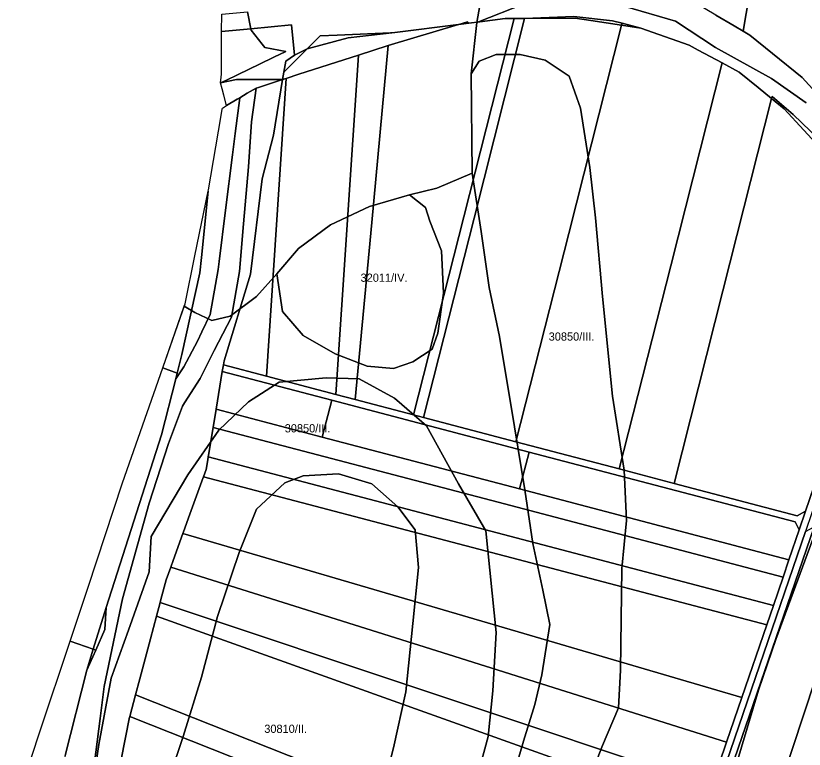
# Model space of a CAD drawing. Extents: x -545779 to -541342, y -1153413 to -1149956.
# Drawn here: x -545548.8 to -545068.2, y -1151704.2 to -1151257.3 of the extents above; entities that cross this region are included whole.
import ezdxf

# ---------------------------------------------------------------- set-up
doc = ezdxf.new("R2010")
doc.units = 0
for name, color, linetype in [('95560013', 7, 'Continuous'), ('95640013', 7, 'Continuous'), ('95660013', 7, 'Continuous')]:
    doc.layers.add(name, color=color, linetype=linetype)

msp = doc.modelspace()

# ---------------------------------------------------------------- linework, layer by layer
at = {"layer": '95560013'}
for points in [[(-545105.44, -1151266.77), (-545111.01, -1151263.46), (-545122.03, -1151256.92), (-545136.05, -1151248.6), (-545152.78, -1151242.45), (-545125.33, -1151080.16), (-545122.66, -1151081.28), (-545114.24, -1151089.6), (-545080.32, -1151118.3)], [(-545105.44, -1151266.77), (-545080.32, -1151118.3), (-545073, -1151124.65), (-545057.67, -1151127.49), (-544996.34, -1151140.83), (-544980.98, -1151144.11), (-544998.72, -1151249.04), (-545016.45, -1151353.98), (-545028.49, -1151339.4), (-545040.16, -1151326.96), (-545069.42, -1151294.93), (-545087.51, -1151280.35), (-545101.41, -1151269.18)], [(-545341.9, -1151491.18), (-545331.84, -1151383.26), (-545321.78, -1151275.35), (-545278.9, -1151262.69), (-545278.74, -1151262.67), (-545272.62, -1151261.89), (-545265.88, -1151261.04), (-545250.45, -1151259.08), (-545245.08, -1151259.05), (-545275.68, -1151379.8), (-545306.28, -1151500.54)], [(-545300.24, -1151502.13), (-545306.28, -1151500.54), (-545275.68, -1151379.8), (-545245.08, -1151259.05), (-545238.63, -1151259.02), (-545269.44, -1151380.59)], [(-545211.74, -1151390), (-545243.89, -1151516.92), (-545300.24, -1151502.13), (-545269.44, -1151380.59), (-545238.63, -1151259.02), (-545207.88, -1151258.87), (-545198.34, -1151260.29), (-545179.58, -1151263.09)], [(-545179.58, -1151263.09), (-545198.34, -1151260.29), (-545207.88, -1151258.87), (-545238.63, -1151259.02), (-545208.57, -1151257.76), (-545185.16, -1151260.43), (-545179.22, -1151261.77)], [(-545243.89, -1151516.92), (-545211.74, -1151390), (-545179.58, -1151263.09), (-545167.85, -1151264.84), (-545138.31, -1151275.29), (-545132.85, -1151278.22), (-545118.25, -1151286.07), (-545149.6, -1151409.76), (-545180.94, -1151533.46)], [(-545179.22, -1151261.77), (-545167.85, -1151264.84), (-545179.58, -1151263.09)], [(-545353.72, -1151488.08), (-545346.84, -1151384.66), (-545339.96, -1151281.24), (-545321.78, -1151275.35), (-545331.84, -1151383.26), (-545341.9, -1151491.18)], [(-545383.88, -1151295.49), (-545376.24, -1151293.01), (-545339.96, -1151281.24), (-545346.84, -1151384.66), (-545353.72, -1151488.08), (-545395.95, -1151476.99)], [(-545088.13, -1151307.69), (-545117.85, -1151424.96), (-545147.56, -1151542.22), (-545180.94, -1151533.46), (-545149.6, -1151409.76), (-545118.25, -1151286.07), (-545107.82, -1151291.69), (-545096.27, -1151301.07)], [(-545395.95, -1151476.99), (-545422.24, -1151470.08), (-545421.84, -1151467.66), (-545405.63, -1151414.68), (-545398.51, -1151356.6), (-545391.7, -1151330.15), (-545386.1, -1151296.21), (-545383.88, -1151295.49)], [(-545117.85, -1151424.96), (-545088.13, -1151307.69), (-545080.42, -1151313.96), (-545056.42, -1151339.95), (-545053.76, -1151337.82), (-545025.81, -1151369.75), (-545008.85, -1151387.91), (-545006.29, -1151390.65), (-545009.39, -1151394.9), (-545013.92, -1151403.14), (-545067.37, -1151559.16), (-545072.53, -1151561.93), (-545147.56, -1151542.22)], [(-545088.13, -1151307.69), (-545087.79, -1151306.45), (-545074.93, -1151317.57), (-545053.76, -1151337.82), (-545056.42, -1151339.95), (-545080.42, -1151313.96)], [(-545435.55, -1151404.58), (-545436.51, -1151413.99), (-545447.54, -1151463.8), (-545450.39, -1151475.03), (-545459.21, -1151471.92), (-545445.56, -1151432.84), (-545439.54, -1151403.64), (-545431.41, -1151364.18)], [(-545483.62, -1151541.82), (-545459.21, -1151471.92), (-545450.39, -1151475.03), (-545451.29, -1151478.56), (-545459.97, -1151512.72), (-545493.67, -1151617.78), (-545501.5, -1151643.33), (-545515.65, -1151638.33), (-545504.73, -1151605.43)], [(-545422.89, -1151474.04), (-545356.22, -1151491.55), (-545362.12, -1151514.04), (-545426.68, -1151497.08)], [(-545356.22, -1151491.55), (-545235.85, -1151523.17), (-545241.75, -1151545.65), (-545362.12, -1151514.04)], [(-545077.52, -1151588.8), (-545081.15, -1151599.39), (-545254.82, -1151553.77), (-545428.5, -1151508.15), (-545426.68, -1151497.08), (-545362.12, -1151514.04), (-545241.75, -1151545.65)], [(-545431.27, -1151525), (-545428.5, -1151508.15), (-545254.82, -1151553.77), (-545081.15, -1151599.39), (-545087.03, -1151616.54), (-545259.25, -1151571.3), (-545431.45, -1151526.07)], [(-545077.52, -1151588.8), (-545241.75, -1151545.65), (-545235.85, -1151523.17), (-545073.83, -1151565.72), (-545071.26, -1151570.52)], [(-545431.45, -1151526.07), (-545259.25, -1151571.3), (-545087.03, -1151616.54), (-545091.07, -1151628.34), (-545262.7, -1151583.26), (-545434.33, -1151538.18), (-545432.72, -1151533.76), (-545431.75, -1151527.89)], [(-545438.56, -1151549.82), (-545434.51, -1151538.69), (-545434.33, -1151538.18), (-545262.7, -1151583.26), (-545091.07, -1151628.34), (-545106.29, -1151672.76), (-545276.56, -1151622.74), (-545446.88, -1151572.71), (-545446.56, -1151571.82), (-545442.62, -1151560.97)], [(-545284.96, -1151646.54), (-545454.33, -1151593.19), (-545452.86, -1151589.14), (-545446.88, -1151572.71), (-545276.56, -1151622.74), (-545106.29, -1151672.76), (-545115.58, -1151699.9)], [(-545113.09, -1151717.19), (-545062.25, -1151568.76), (-545033.36, -1151576.36), (-545082.55, -1151725.21)], [(-545049.99, -1151733.77), (-545082.55, -1151725.21), (-545033.36, -1151576.36), (-544999.15, -1151585.34)], [(-545454.33, -1151593.19), (-545284.96, -1151646.54), (-545115.58, -1151699.9), (-545124.81, -1151726.84), (-545292.82, -1151670.78), (-545460.83, -1151614.73), (-545460.35, -1151612.94), (-545457.17, -1151600.98)], [(-545292.82, -1151670.78), (-545124.81, -1151726.84), (-545130.08, -1151742.23), (-545296.58, -1151682.7), (-545463.08, -1151623.18), (-545460.83, -1151614.73)], [(-545463.08, -1151623.18), (-545296.58, -1151682.7), (-545130.08, -1151742.23), (-545149.99, -1151800.34), (-545312.92, -1151735.72), (-545475.85, -1151671.11), (-545473.22, -1151661.24), (-545466.73, -1151636.88)], [(-545548.76, -1151738.09), (-545534.01, -1151693.64), (-545515.65, -1151638.33), (-545501.5, -1151643.33), (-545505.41, -1151656.08), (-545518.57, -1151708.09), (-545528.01, -1151745.41)], [(-545475.85, -1151671.11), (-545312.92, -1151735.72), (-545149.99, -1151800.34), (-545154.36, -1151813.1), (-545316.85, -1151748.66), (-545479.34, -1151684.22)], [(-545316.85, -1151748.66), (-545154.36, -1151813.1), (-545165.44, -1151845.43), (-545324.94, -1151777.98), (-545484.43, -1151710.54), (-545479.48, -1151684.74), (-545479.34, -1151684.22)]]:
    msp.add_lwpolyline(points, close=True, dxfattribs=at)
at = {"layer": '95640013'}
for points in [[(-545405.56, -1151265.22), (-545423.3, -1151266.92), (-545423.26, -1151256.45), (-545407.59, -1151255.04)], [(-545386.1, -1151296.21), (-545400.62, -1151296.21), (-545413.27, -1151296.21), (-545414.2, -1151296.21), (-545423.96, -1151298.24), (-545420.77, -1151296.7), (-545413.14, -1151293.02), (-545400.24, -1151286.81), (-545391.48, -1151282.59), (-545384.07, -1151279.02), (-545396.97, -1151276.67), (-545398.57, -1151274.66), (-545405.38, -1151266.13), (-545405.56, -1151265.22), (-545380.63, -1151262.83), (-545378.85, -1151281.43), (-545384.1, -1151284.91), (-545385.35, -1151291.69)], [(-545423.39, -1151292.93), (-545423.31, -1151270.45), (-545423.3, -1151266.92), (-545405.56, -1151265.22), (-545405.38, -1151266.13), (-545398.57, -1151274.66), (-545396.97, -1151276.67), (-545384.07, -1151279.02), (-545391.48, -1151282.59), (-545400.24, -1151286.81), (-545413.14, -1151293.02), (-545420.77, -1151296.7), (-545423.96, -1151298.24), (-545423.59, -1151294.79)], [(-545371.14, -1151277.39), (-545346.1, -1151270.79), (-545317.83, -1151267.63), (-545278.9, -1151262.69), (-545321.78, -1151275.35), (-545339.96, -1151281.24), (-545376.24, -1151293.01), (-545383.88, -1151295.49), (-545386.1, -1151296.21), (-545385.35, -1151291.69)], [(-545273.36, -1151261.1), (-545272.62, -1151261.89), (-545278.74, -1151262.67)], [(-545367.54, -1151273.77), (-545363.32, -1151269.53), (-545352.8, -1151269.09), (-545320.46, -1151267.74), (-545317.83, -1151267.63), (-545346.1, -1151270.79), (-545371.14, -1151277.39)], [(-545371.14, -1151277.39), (-545385.35, -1151291.69), (-545384.1, -1151284.91), (-545378.85, -1151281.43)], [(-545407.65, -1151304.59), (-545412.21, -1151307.26), (-545413.77, -1151308.17), (-545420.31, -1151312), (-545421.95, -1151305.81), (-545423.02, -1151301.8), (-545423.96, -1151298.24), (-545414.2, -1151296.21), (-545413.27, -1151296.21), (-545400.62, -1151296.21), (-545386.1, -1151296.21), (-545400.91, -1151301.01), (-545402.34, -1151301.48)], [(-545435.3, -1151449.8), (-545438.1, -1151455.66), (-545446.32, -1151471.25), (-545451.29, -1151478.56), (-545450.39, -1151475.03), (-545447.54, -1151463.8), (-545436.51, -1151413.99), (-545435.55, -1151404.58), (-545431.41, -1151364.18), (-545431.24, -1151363.35), (-545423.77, -1151319.26), (-545422.93, -1151314.27), (-545422.82, -1151313.65), (-545420.31, -1151312), (-545413.77, -1151308.17), (-545412.21, -1151307.26), (-545414.99, -1151329.16), (-545416.61, -1151341.97), (-545420.9, -1151375.73), (-545424.87, -1151407.08), (-545425.36, -1151411.99), (-545430.26, -1151439.25)], [(-545395.95, -1151476.99), (-545353.72, -1151488.08), (-545341.9, -1151491.18), (-545306.28, -1151500.54), (-545300.24, -1151502.13), (-545243.89, -1151516.92), (-545180.94, -1151533.46), (-545147.56, -1151542.22), (-545072.53, -1151561.93), (-545067.37, -1151559.16), (-545071.26, -1151570.52), (-545073.83, -1151565.72), (-545235.85, -1151523.17), (-545356.22, -1151491.55), (-545422.89, -1151474.04), (-545422.24, -1151470.08)], [(-545067.43, -1151571.53), (-545062.25, -1151568.76), (-545113.09, -1151717.19), (-545166.57, -1151873.32), (-545168.93, -1151867.91), (-545118.18, -1151719.72)], [(-545493.67, -1151617.78), (-545494.5, -1151631.31), (-545500.02, -1151643.85), (-545501.5, -1151643.33)], [(-545501.5, -1151643.33), (-545500.02, -1151643.85), (-545505.41, -1151656.08)]]:
    msp.add_lwpolyline(points, close=True, dxfattribs=at)
for points in [[(-545053.76, -1151337.82), (-545074.93, -1151317.57), (-545087.79, -1151306.45), (-545088.13, -1151307.69), (-545096.27, -1151301.07), (-545107.82, -1151291.69), (-545118.25, -1151286.07), (-545132.85, -1151278.22), (-545138.31, -1151275.29), (-545167.85, -1151264.84), (-545179.22, -1151261.77), (-545185.16, -1151260.43), (-545208.57, -1151257.76), (-545238.63, -1151259.02), (-545245.08, -1151259.05), (-545250.45, -1151259.08), (-545265.88, -1151261.04), (-545272.62, -1151261.89), (-545273.36, -1151261.1), (-545278.74, -1151262.67), (-545278.9, -1151262.69), (-545317.83, -1151267.63), (-545320.46, -1151267.74), (-545352.8, -1151269.09), (-545363.32, -1151269.53), (-545367.54, -1151273.77), (-545371.14, -1151277.39), (-545378.85, -1151281.43), (-545380.63, -1151262.83), (-545405.56, -1151265.22), (-545407.59, -1151255.04)], [(-545122.03, -1151256.92), (-545111.01, -1151263.46), (-545105.44, -1151266.77), (-545101.41, -1151269.18), (-545087.51, -1151280.35), (-545069.42, -1151294.93), (-545040.16, -1151326.96)], [(-545502.66, -1151726.56), (-545497.42, -1151685.55), (-545494.92, -1151666.02), (-545483.76, -1151612.67), (-545467.52, -1151554.19), (-545455.66, -1151518.02), (-545447.22, -1151495.22), (-545445.92, -1151493.18), (-545436.41, -1151478.25), (-545428.6, -1151462.98), (-545427.77, -1151461.35), (-545417.33, -1151440.92), (-545412.41, -1151413.05), (-545409.9, -1151384.14), (-545406.87, -1151349.35), (-545405.01, -1151321.93), (-545402.34, -1151301.48), (-545400.91, -1151301.01), (-545386.1, -1151296.21), (-545391.7, -1151330.15), (-545398.51, -1151356.6), (-545405.63, -1151414.68), (-545421.84, -1151467.66), (-545422.24, -1151470.08), (-545422.89, -1151474.04), (-545426.68, -1151497.08), (-545428.5, -1151508.15), (-545431.27, -1151525), (-545431.45, -1151526.07), (-545431.75, -1151527.89), (-545432.72, -1151533.76), (-545434.33, -1151538.18), (-545434.51, -1151538.69), (-545438.56, -1151549.82), (-545442.62, -1151560.97), (-545446.56, -1151571.82), (-545446.88, -1151572.71), (-545452.86, -1151589.14), (-545454.33, -1151593.19), (-545457.17, -1151600.98), (-545460.35, -1151612.94), (-545460.83, -1151614.73), (-545463.08, -1151623.18), (-545466.73, -1151636.88), (-545473.22, -1151661.24), (-545475.85, -1151671.11), (-545479.34, -1151684.22), (-545479.48, -1151684.74), (-545484.43, -1151710.54)], [(-545518.57, -1151708.09), (-545505.41, -1151656.08), (-545500.02, -1151643.85), (-545494.5, -1151631.31), (-545493.67, -1151617.78), (-545459.97, -1151512.72), (-545451.29, -1151478.56), (-545446.32, -1151471.25), (-545438.1, -1151455.66), (-545435.3, -1151449.8), (-545430.26, -1151439.25), (-545425.36, -1151411.99), (-545424.87, -1151407.08), (-545420.9, -1151375.73), (-545416.61, -1151341.97), (-545414.99, -1151329.16), (-545412.21, -1151307.26), (-545407.65, -1151304.59), (-545402.34, -1151301.48), (-545405.01, -1151321.93), (-545406.87, -1151349.35), (-545409.9, -1151384.14), (-545412.41, -1151413.05), (-545417.33, -1151440.92), (-545427.77, -1151461.35), (-545428.6, -1151462.98), (-545436.41, -1151478.25), (-545445.92, -1151493.18), (-545447.22, -1151495.22), (-545455.66, -1151518.02), (-545467.52, -1151554.19), (-545483.76, -1151612.67), (-545494.92, -1151666.02), (-545497.42, -1151685.55), (-545502.66, -1151726.56)], [(-545124.81, -1151726.84), (-545115.58, -1151699.9), (-545106.29, -1151672.76), (-545091.07, -1151628.34), (-545087.03, -1151616.54), (-545081.15, -1151599.39), (-545077.52, -1151588.8), (-545071.26, -1151570.52), (-545067.37, -1151559.16), (-545013.92, -1151403.14), (-545009.39, -1151394.9), (-545006.29, -1151390.65), (-545003.62, -1151393.78), (-545006.01, -1151397.05), (-545010.42, -1151405.07), (-545063.52, -1151560.13), (-545067.43, -1151571.53), (-545118.18, -1151719.72)]]:
    msp.add_lwpolyline(points, dxfattribs=at)
at = {"layer": '95660013'}
for points in [[(-545067.132, -1151310.344), (-545088.243, -1151295.525), (-545122.346, -1151276.734), (-545146.706, -1151260.726), (-545177.329, -1151251.678), (-545211.432, -1151248.895), (-545237.879, -1151249.591), (-545267.807, -1151261.422), (-545262.934, -1151233.583), (-545251.798, -1151198.088), (-545230.224, -1151176.512), (-545201.689, -1151161.897), (-545169.673, -1151153.545), (-545145.314, -1151152.849), (-545113.298, -1151154.937), (-545085.46, -1151157.721), (-545062.028, -1151157.228)], [(-545262.934, -1151233.583), (-545267.807, -1151261.422), (-545271.287, -1151292.741), (-545270.59, -1151353.292), (-545292.164, -1151362.34), (-545308.87, -1151366.515), (-545333.228, -1151373.475), (-545356.893, -1151384.611), (-545376.379, -1151399.227), (-545389.603, -1151414.538), (-545402.131, -1151428.458), (-545418.138, -1151440.29), (-545429.274, -1151443.073), (-545439.713, -1151438.202), (-545446.038, -1151434.208), (-545445.56, -1151432.84), (-545439.54, -1151403.64), (-545431.41, -1151364.18), (-545431.24, -1151363.35), (-545423.77, -1151319.26), (-545422.93, -1151314.27), (-545422.82, -1151313.65), (-545420.31, -1151312), (-545421.95, -1151305.81), (-545423.02, -1151301.8), (-545423.96, -1151298.24), (-545423.59, -1151294.79), (-545423.39, -1151292.93), (-545423.31, -1151270.45), (-545423.3, -1151266.92), (-545423.26, -1151256.45)], [(-545195.8, -1151713.941), (-545191.248, -1151701.979), (-545181.504, -1151679.011), (-545180.112, -1151656.044), (-545179.417, -1151594.101), (-545176.632, -1151564.87), (-545178.024, -1151534.247), (-545184.985, -1151489.008), (-545191.248, -1151428.458), (-545195.425, -1151380.435), (-545198.903, -1151349.812), (-545204.471, -1151313.621), (-545211.432, -1151294.133), (-545226.048, -1151284.39), (-545241.36, -1151280.91), (-545255.974, -1151280.91), (-545266.414, -1151285.086), (-545271.287, -1151292.741), (-545267.807, -1151261.422), (-545237.879, -1151249.591)], [(-545177.329, -1151251.678), (-545146.706, -1151260.726), (-545122.346, -1151276.734), (-545088.243, -1151295.525), (-545067.132, -1151310.344)], [(-545252.002, -1151742.592), (-545239.272, -1151699.195), (-545232.311, -1151676.923), (-545228.136, -1151658.828), (-545223.263, -1151628.205), (-545227.439, -1151607.325), (-545233.704, -1151578.79), (-545238.575, -1151546.079), (-545244.84, -1151507.8), (-545253.886, -1151452.817), (-545260.151, -1151422.89), (-545265.022, -1151388.787), (-545270.59, -1151353.292), (-545271.287, -1151292.741), (-545266.414, -1151285.086), (-545255.974, -1151280.91), (-545241.36, -1151280.91), (-545226.048, -1151284.39), (-545211.432, -1151294.133), (-545204.471, -1151313.621), (-545198.903, -1151349.812), (-545195.425, -1151380.435), (-545191.248, -1151428.458), (-545184.985, -1151489.008), (-545178.024, -1151534.247), (-545176.632, -1151564.87), (-545179.417, -1151594.101), (-545180.112, -1151656.044), (-545181.504, -1151679.011), (-545191.248, -1151701.979), (-545195.8, -1151713.941)], [(-545548.76, -1151738.09), (-545534.01, -1151693.64), (-545515.65, -1151638.33), (-545504.73, -1151605.43), (-545483.62, -1151541.82), (-545459.21, -1151471.92), (-545446.038, -1151434.208), (-545439.713, -1151438.202), (-545429.274, -1151443.073), (-545418.138, -1151440.29), (-545402.131, -1151428.458), (-545389.603, -1151414.538), (-545386.123, -1151437.506), (-545373.596, -1151452.121), (-545354.107, -1151463.257), (-545334.621, -1151470.913), (-545318.614, -1151472.305), (-545306.781, -1151468.129), (-545294.95, -1151460.473), (-545291.469, -1151450.729), (-545287.989, -1151426.37), (-545289.382, -1151400.619), (-545296.342, -1151382.523), (-545299.125, -1151374.171), (-545308.87, -1151366.515), (-545292.164, -1151362.34), (-545270.59, -1151353.292), (-545265.022, -1151388.787), (-545260.151, -1151422.89), (-545253.886, -1151452.817), (-545244.84, -1151507.8), (-545238.575, -1151546.079), (-545233.704, -1151578.79), (-545227.439, -1151607.325), (-545223.263, -1151628.205), (-545228.136, -1151658.828), (-545232.311, -1151676.923), (-545239.272, -1151699.195), (-545252.002, -1151742.592)], [(-545270.186, -1151731.021), (-545260.846, -1151696.411), (-545258.061, -1151668.571), (-545255.974, -1151633.076), (-545262.239, -1151571.134), (-545278.943, -1151542.599), (-545298.43, -1151507.104), (-545317.917, -1151490.4), (-545339.493, -1151478.569), (-545359.675, -1151477.873), (-545388.21, -1151480.656), (-545407.002, -1151492.488), (-545425.099, -1151509.888), (-545443.89, -1151537.031), (-545466.162, -1151574.614), (-545467.553, -1151596.189), (-545480.081, -1151631.684), (-545490.52, -1151660.916), (-545498.175, -1151701.283), (-545501.048, -1151720.553)], [(-545501.048, -1151720.553), (-545498.175, -1151701.283), (-545490.52, -1151660.916), (-545480.081, -1151631.684), (-545467.553, -1151596.189), (-545466.162, -1151574.614), (-545443.89, -1151537.031), (-545425.099, -1151509.888), (-545407.002, -1151492.488), (-545388.21, -1151480.656), (-545359.675, -1151477.873), (-545339.493, -1151478.569), (-545317.917, -1151490.4), (-545298.43, -1151507.104), (-545278.943, -1151542.599), (-545262.239, -1151571.134), (-545255.974, -1151633.076), (-545258.061, -1151668.571), (-545260.846, -1151696.411), (-545270.186, -1151731.021)], [(-545463.028, -1151744.796), (-545446.673, -1151696.411), (-545435.539, -1151660.22), (-545425.794, -1151623.333), (-545412.57, -1151584.358), (-545402.131, -1151557.91), (-545384.732, -1151541.903), (-545373.596, -1151537.727), (-545352.02, -1151536.335), (-545331.835, -1151542.599), (-545315.829, -1151556.518), (-545305.39, -1151570.438), (-545303.3, -1151593.405), (-545306.781, -1151627.509), (-545310.958, -1151669.267), (-545318.614, -1151703.371), (-545325.835, -1151731.572)], [(-545325.835, -1151731.572), (-545318.614, -1151703.371), (-545310.958, -1151669.267), (-545306.781, -1151627.509), (-545303.3, -1151593.405), (-545305.39, -1151570.438), (-545315.829, -1151556.518), (-545331.835, -1151542.599), (-545352.02, -1151536.335), (-545373.596, -1151537.727), (-545384.732, -1151541.903), (-545402.131, -1151557.91), (-545412.57, -1151584.358), (-545425.794, -1151623.333), (-545435.539, -1151660.22), (-545446.673, -1151696.411), (-545463.028, -1151744.796)], [(-545058.607, -1151564.624), (-545085.605, -1151637.354), (-545096.074, -1151668.209), (-545106.542, -1151702.921), (-545114.807, -1151731.021)], [(-545114.807, -1151731.021), (-545106.542, -1151702.921), (-545096.074, -1151668.209), (-545085.605, -1151637.354), (-545058.607, -1151564.624)]]:
    msp.add_lwpolyline(points, dxfattribs=at)
msp.add_lwpolyline([(-545373.596, -1151452.121), (-545386.123, -1151437.506), (-545389.603, -1151414.538), (-545376.379, -1151399.227), (-545356.893, -1151384.611), (-545333.228, -1151373.475), (-545308.87, -1151366.515), (-545299.125, -1151374.171), (-545296.342, -1151382.523), (-545289.382, -1151400.619), (-545287.989, -1151426.37), (-545291.469, -1151450.729), (-545294.95, -1151460.473), (-545306.781, -1151468.129), (-545318.614, -1151472.305), (-545334.621, -1151470.913), (-545354.107, -1151463.257)], close=True, dxfattribs=at)

# ---------------------------------------------------------------- texts
for s, rotation, p in [('32011/IV.', 0, (-545338.615, -1151419.41)), ('30850/III.', 360, (-545223.96, -1151455.252)), ('30850/III.', 360, (-545384.848, -1151511.169)), ('30810/II.', 360, (-545397.302, -1151694.249))]:
    msp.add_text(s, height=5, rotation=rotation, dxfattribs=at).set_placement(p)

doc.saveas('drawing.dxf')
